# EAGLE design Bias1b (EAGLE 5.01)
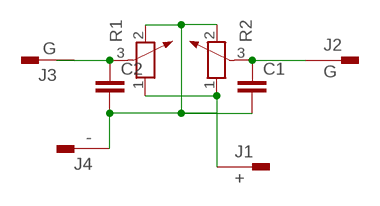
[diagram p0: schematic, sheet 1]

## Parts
C1  C-EU275-113X316  [C275-113X316]
C2  C-EU275-113X316  [C275-113X316]
J1  +  PIN2F061.200  [F061.200]
J2  G  PIN2F061.200  [F061.200]
J3  G  PIN2F061.200  [F061.200]
J4  -  PIN2F061.200  [F061.200]
R1  POTENTIOMETER_PT_SPIN  [PT-SPIN]
R2  POTENTIOMETER_PT_SPIN  [PT-SPIN]

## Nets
N$1: C1.1 J2.1A R2.3
N$3: C2.1 J3.1A J3.1B(1.1) R1.3
N$4: C1.2 C2.2 J4.1A R1.2 R2.2
N$6: J1.1A R1.1 R2.1
Unconnected: J1.1B(1.1) J2.1B(1.1) J4.1B(1.1)

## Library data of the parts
C1 C2 = rcl:C-EU: CAPACITOR, European symbol
J1-J4 = con-faston:PIN2: Flachstecker Typ Tyco/Electronics/AMP TAB, FASTON
R1 R2 = rcl:POTENTIOMETER_: Potentiometer

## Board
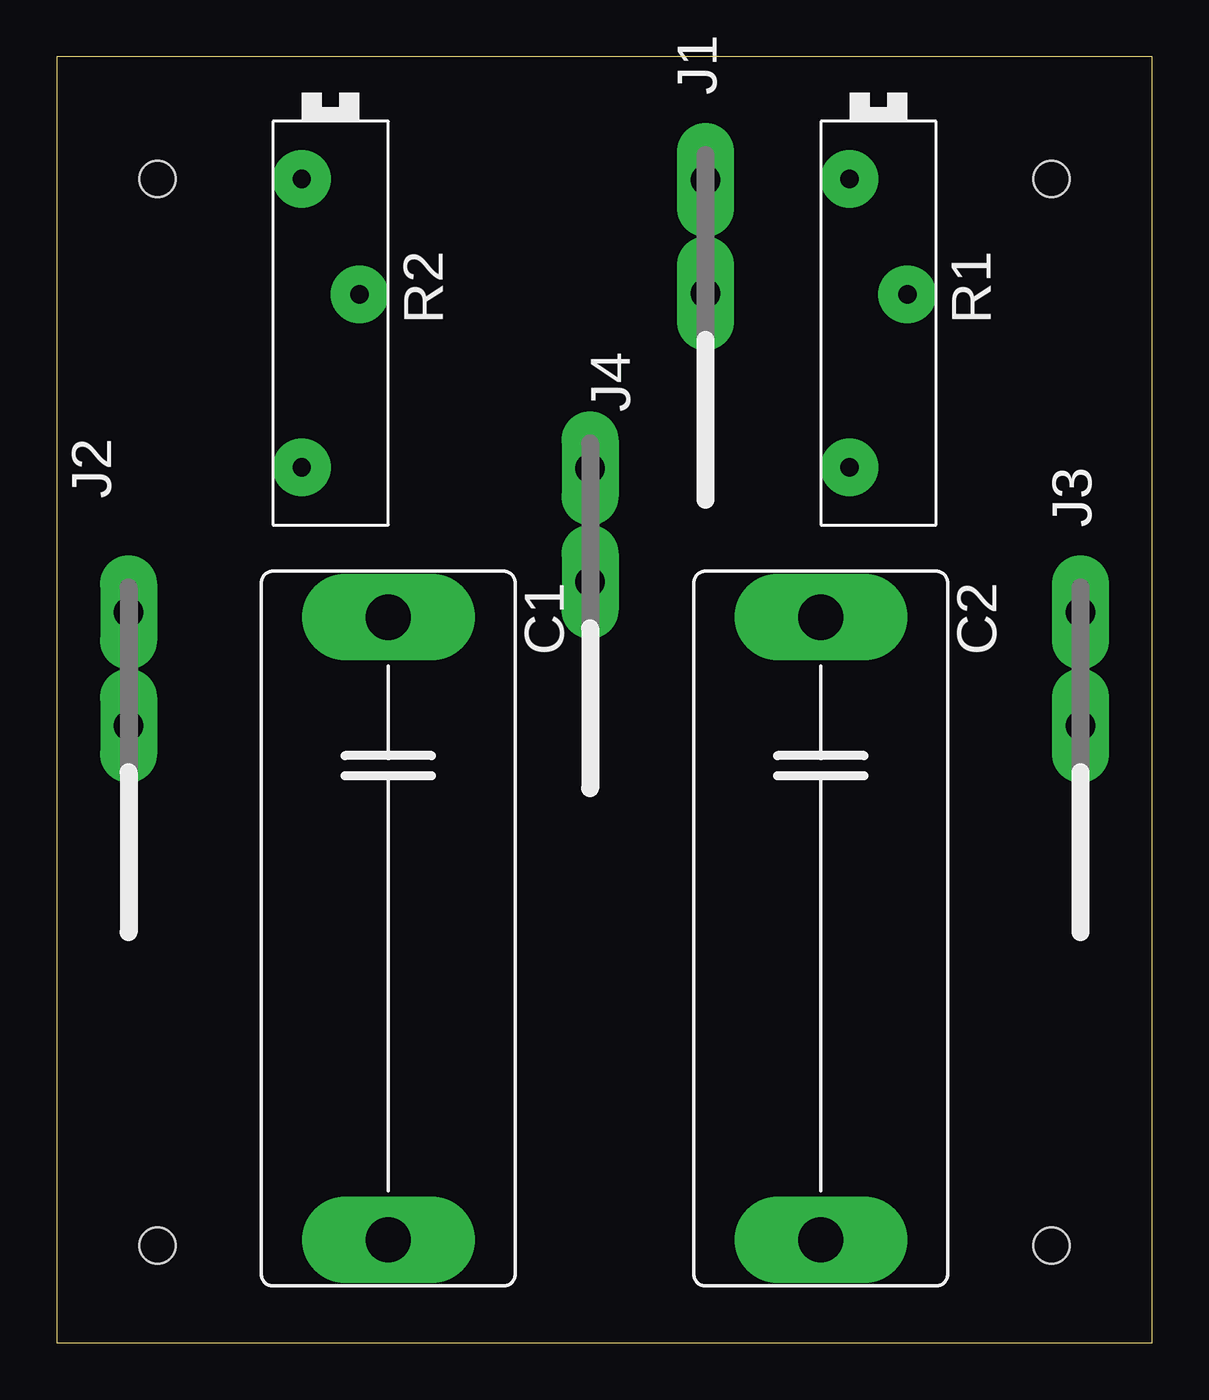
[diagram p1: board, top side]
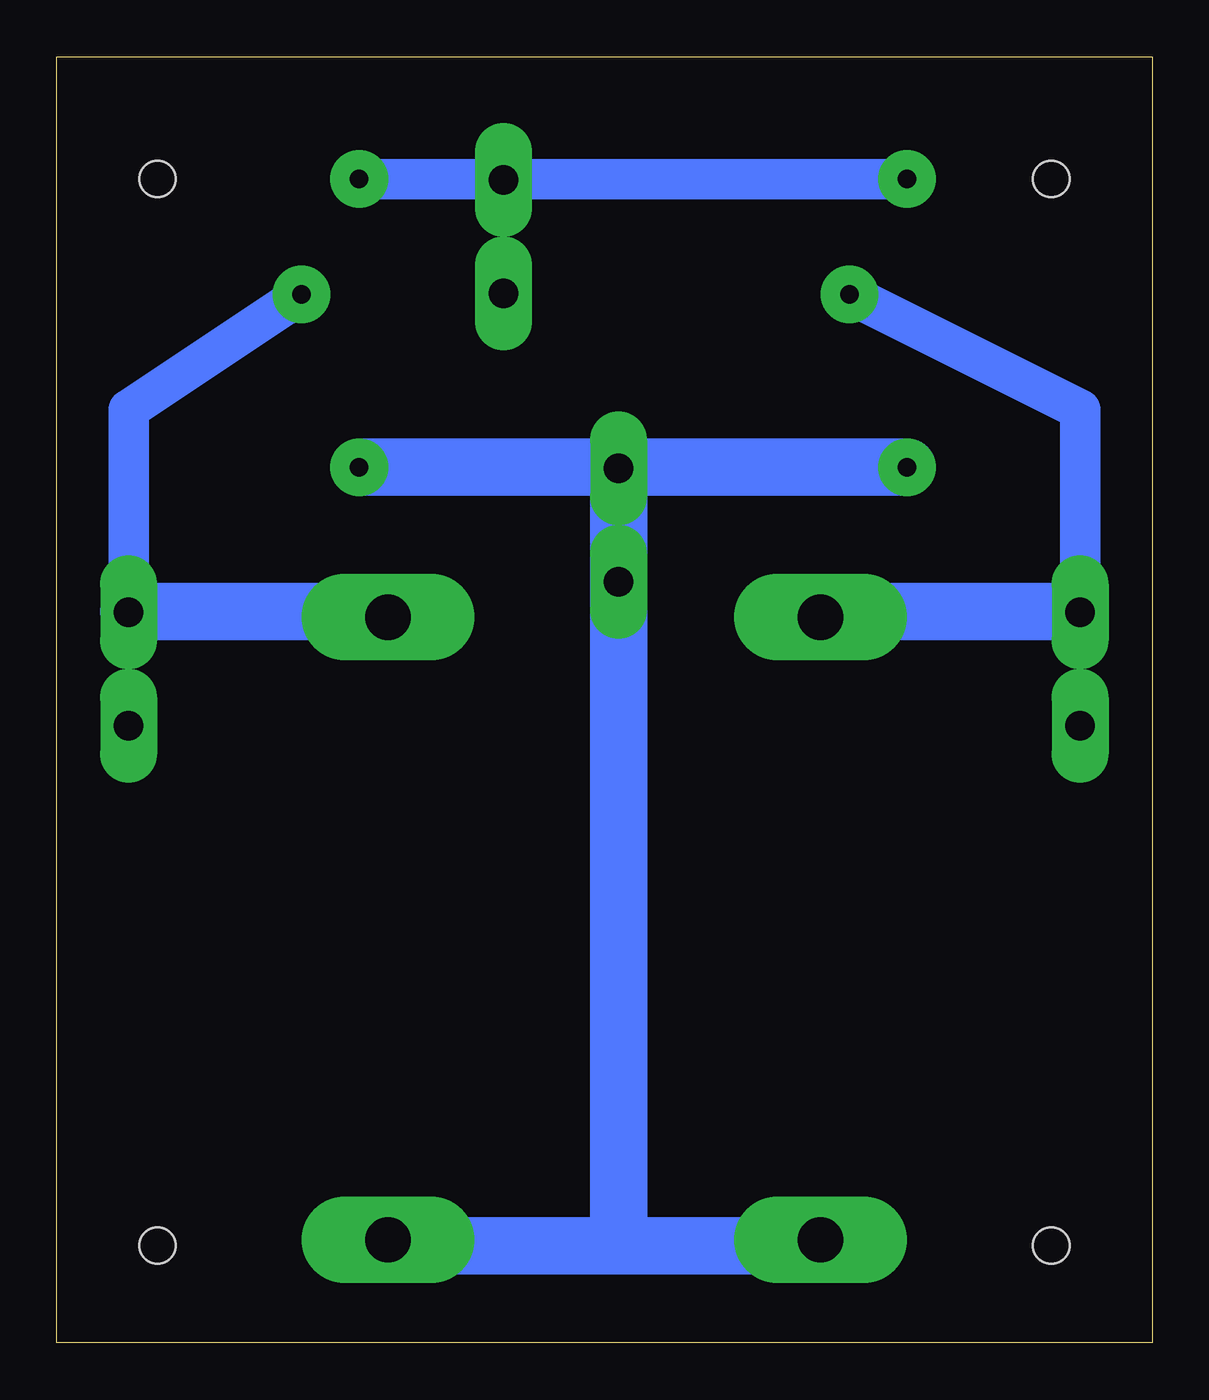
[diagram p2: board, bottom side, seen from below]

Size 48.24 x 56.66 mm. Coordinates in mm from the lower left corner, seen from the top.
Outline: 0,0 48.24,0 48.24,56.66 0,56.66 0,0
Copper layers (1*16): Top 0.035mm / dielectric 1.5mm / Bottom 0.035mm
Design rules "default": minimum track width 10mil, minimum drill 24mil, track to track 8mil, track to pad 8mil, pad to pad 8mil, via to via 8mil, smd to smd 8mil, copper to edge 40mil, drill to drill 8mil, minimum pad ring 10mil, minimum via ring 8mil, stop-mask expansion 4mil, vias tented up to drill 0mil, thermal gap 10mil
Holes 1.6 mm at 4.44,4.28 43.81,4.28 4.44,51.27 43.81,51.27

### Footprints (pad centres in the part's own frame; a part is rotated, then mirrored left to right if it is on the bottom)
C275-113X316 = drill 2 pad 3.81 long: 1 -13.716,0; 2 13.716,0
F061.200 = drill 1.3 pad 2.5 long: 1A -2.5,0; 1B 2.5,0
PT-SPIN = drill 0.813 pad 2.54 round: 1 -6.35,-1.27; 2 6.35,-1.27; 3 -1.27,1.27

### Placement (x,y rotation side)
C1  14.6,18.25 270 top
C2  33.65,18.25 270 top
J1  28.57,48.73 270 top
J2  3.17,29.68 270 top
J3  45.08,29.68 270 top
J4  23.49,36.03 270 top
R1  36.19,44.92 270 top
R2  12.06,44.92 270 top

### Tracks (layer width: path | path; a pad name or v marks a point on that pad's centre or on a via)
N$1
  Bottom 0.254: J2.1A 3.17,32.22
  Bottom 1.778: 12.06,32.22 C1.1 | R2.3 3.17,41.11 3.17,32.22
  Bottom 2.54: 3.17,32.22 12.06,32.22
N$3
  Bottom 0.254: J3.1B J3.1A 45.08,32.22 45.08,33.49
  Bottom 1.778: 45.08,32.22 45.08,41.11 R1.3 | C2.1 36.19,32.22
  Bottom 2.54: 36.19,32.22 45.08,32.22
N$4
  Bottom 0.254: J4.1A 23.49,38.57
  Bottom 1.778: C1.2 17.14,4.28 | 31.11,4.28 C2.2
  Bottom 2.54: R1.2 23.49,38.57 R2.2 | 23.49,4.28 31.11,4.28 | 17.14,4.28 23.49,4.28 | 23.49,4.28 J4.1A
N$6
  Bottom 0.254: 29.84,51.27 J1.1A
  Bottom 1.778: R1.1 29.84,51.27 R2.1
